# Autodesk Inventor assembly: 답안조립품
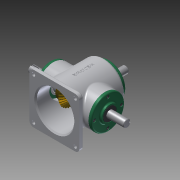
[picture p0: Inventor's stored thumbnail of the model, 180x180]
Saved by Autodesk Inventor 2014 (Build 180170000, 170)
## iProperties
Created: 2015-10
Part Number: 답안조립품
Document SubType Name: Assembly
Designer: aapexcom
Author: aapexcom
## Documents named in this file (14)
- C:\Users\aapexcom\Desktop\451008V1011\답안조립품.iam
- C:\Users\aapexcom\Desktop\451008V1011\답안조립품.ipt
- C:\Users\aapexcom\Desktop\451008V1011\메인 축.ipt
- 메인 축.ipt
- C:\Users\aapexcom\Desktop\451008V1011\베어링 6203.ipt
- C:\Users\aapexcom\Desktop\451008V1011\키 5x5.ipt
- C:\Users\aapexcom\Desktop\451008V1011\메인 베벨기어.ipt
- C:\Users\aapexcom\Desktop\451008V1011\커버.ipt
- C:\Users\aapexcom\Desktop\451008V1011\서브 축.ipt
- 서브 축.ipt
- C:\Users\aapexcom\Desktop\451008V1011\서브 베벨기어.ipt
- C:\Users\aapexcom\Desktop\451008V1011\키 4x4.ipt
- C:\Users\aapexcom\Desktop\451008V1011\오일실.ipt
- C:\Users\aapexcom\Desktop\451008V1011\M4.ipt
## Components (12 placed, 1 different names)
1. M4:1
2. M4:2
3. M4:3
4. M4:4
5. M4:5
6. M4:6
7. M4:7
8. M4:8
9. M4:9
10. M4:10
11. M4:11
12. M4:12
